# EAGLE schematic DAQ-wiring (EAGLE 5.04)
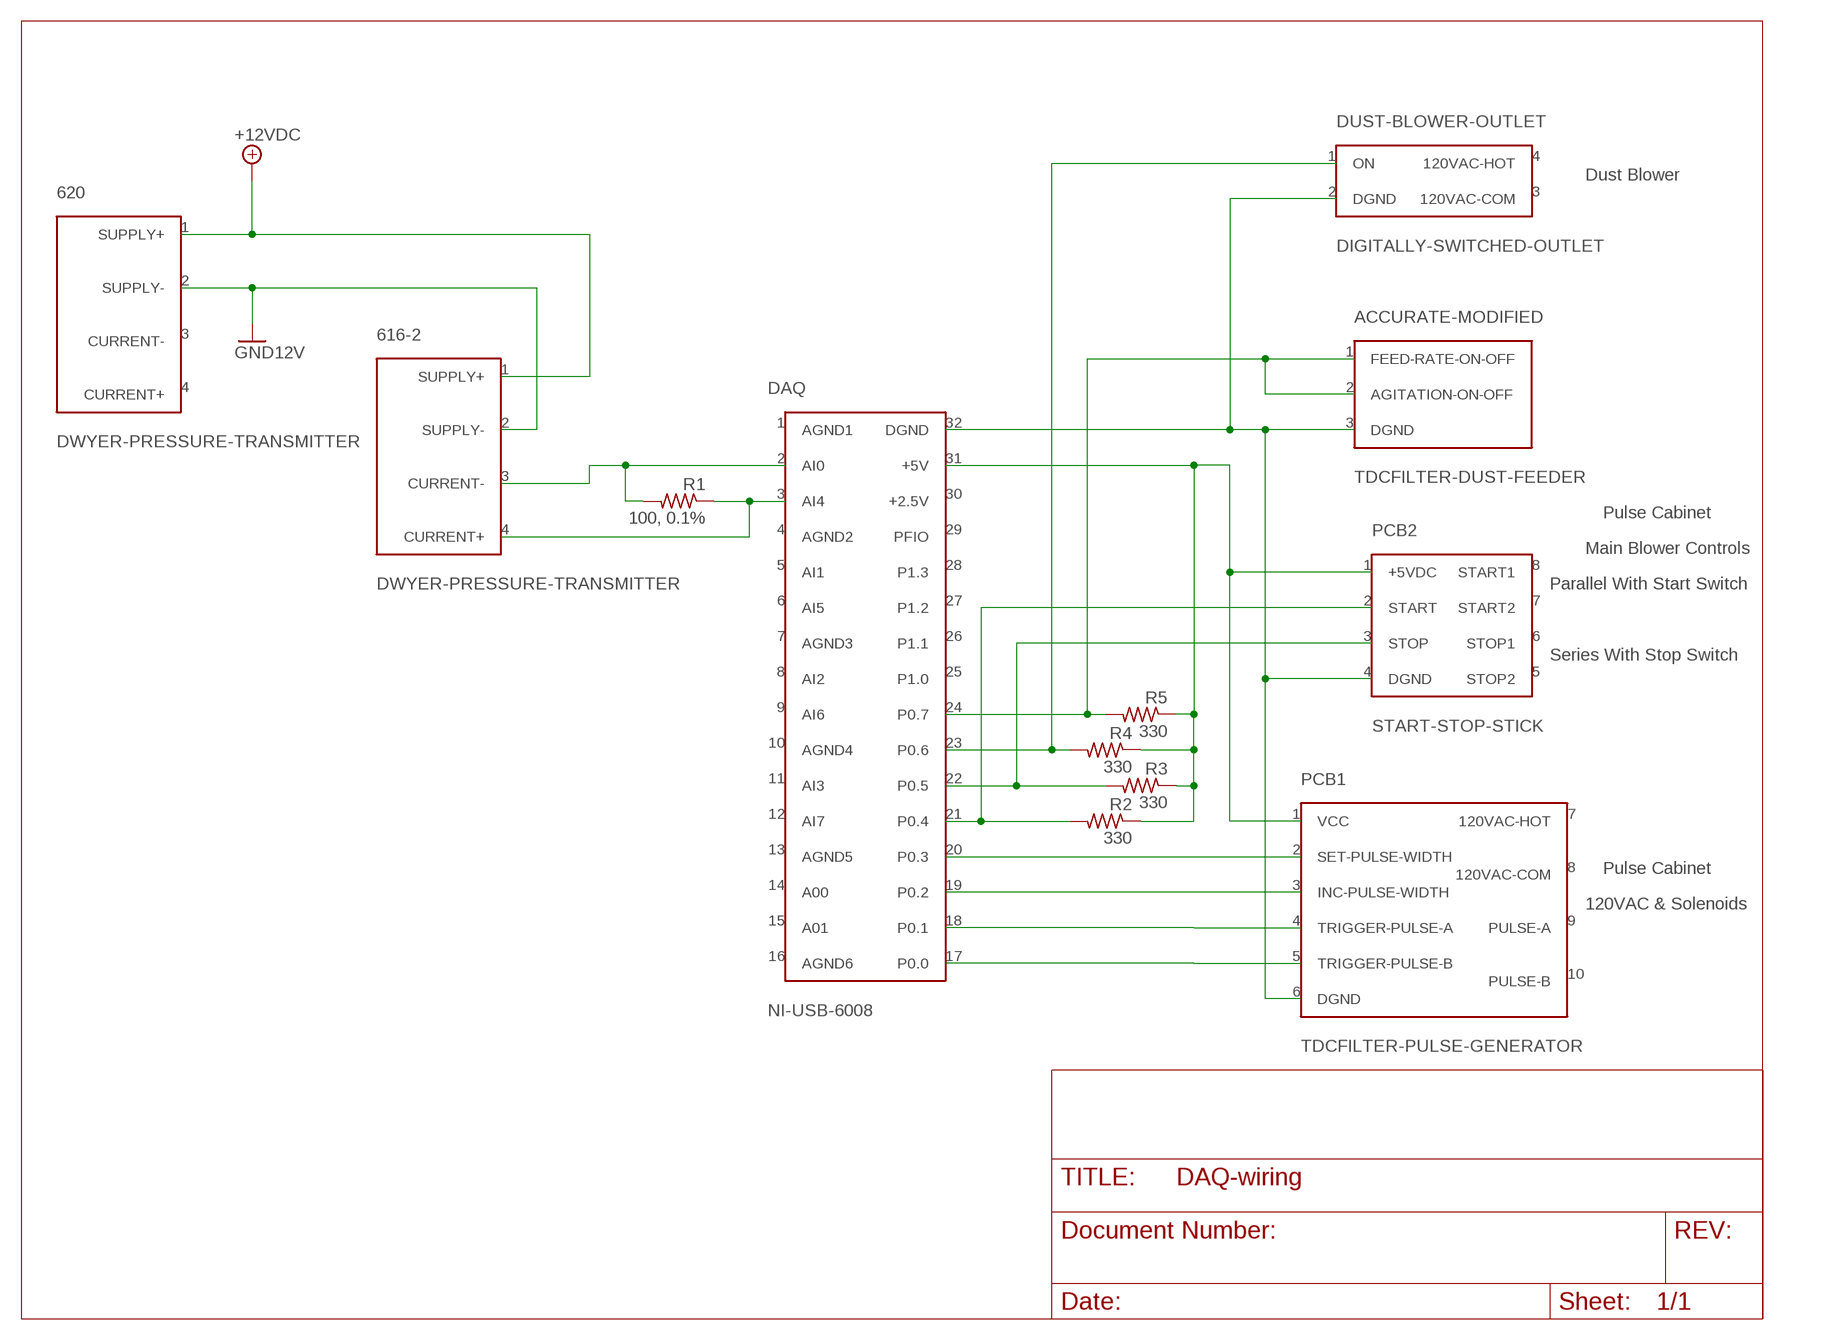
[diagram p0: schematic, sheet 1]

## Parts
616-2  DWYER-PRESSURE-TRANSMITTER  [4SIL]
620  DWYER-PRESSURE-TRANSMITTER  [4SIL]
ACCURATE-MODIFIED  TDCFILTER-DUST-FEEDER  [4SIL]
DAQ  NI-USB-6008  [32DILULTRAWIDE]
DUST-BLOWER-OUTLET  DIGITALLY-SWITCHED-OUTLET  [4DIP]
PCB1  TDCFILTER-PULSE-GENERATOR  [10SILWIDE]
PCB2  START-STOP-STICK  [8DIP]
R1  100, 0.1%  R-US_V234/12  [V234/12]
R2  330  R-US_V234/12  [V234/12]
R3  330  R-US_V234/12  [V234/12]
R4  330  R-US_V234/12  [V234/12]
R5  330  R-US_V234/12  [V234/12]

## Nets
+12V: 616-2.1(SUPPLY+) 620.1(SUPPLY+) ; supply symbol labelled +12VDC
GND: 616-2.2(SUPPLY-) 620.2(SUPPLY-) ; supply symbol labelled GND12V
N$1: 616-2.3(CURRENT-) DAQ.2(AI0) R1.2
N$2: 616-2.4(CURRENT+) DAQ.3(AI4) R1.1
N$3: DAQ.21(P0.4) PCB2.2(START) R2.2
N$4: DAQ.22(P0.5) PCB2.3(STOP) R3.2
N$5: DAQ.23(P0.6) DUST-BLOWER-OUTLET.1(ON) R4.2
N$6: ACCURATE-MODIFIED.1(FEED-RATE-ON-OFF) ACCURATE-MODIFIED.2(AGITATION-ON-OFF) DAQ.24(P0.7) R5.2
N$7: DAQ.31(+5V) PCB1.1(VCC) PCB2.1(+5VDC) R2.1 R3.1 R4.1 R5.1
N$8: ACCURATE-MODIFIED.3(DGND) DAQ.32(DGND) DUST-BLOWER-OUTLET.2(DGND) PCB1.6(DGND) PCB2.4(DGND)
N$9: DAQ.17(P0.0) PCB1.5(TRIGGER-PULSE-B)
N$10: DAQ.18(P0.1) PCB1.4(TRIGGER-PULSE-A)
N$11: DAQ.19(P0.2) PCB1.3(INC-PULSE-WIDTH)
N$12: DAQ.20(P0.3) PCB1.2(SET-PULSE-WIDTH)
Unconnected: 620.3(CURRENT-) 620.4(CURRENT+) DAQ.1(AGND1) DAQ.4(AGND2) DAQ.5(AI1) DAQ.6(AI5) DAQ.7(AGND3) DAQ.8(AI2) DAQ.9(AI6) DAQ.10(AGND4) DAQ.11(AI3) DAQ.12(AI7) DAQ.13(AGND5) DAQ.14(A00) DAQ.15(A01) DAQ.16(AGND6) DAQ.25(P1.0) DAQ.26(P1.1) DAQ.27(P1.2) DAQ.28(P1.3) DAQ.29(PFIO) DAQ.30(+2.5V) DUST-BLOWER-OUTLET.3(120VAC-COM) DUST-BLOWER-OUTLET.4(120VAC-HOT) PCB1.7(120VAC-HOT) PCB1.8(120VAC-COM) PCB1.9(PULSE-A) PCB1.10(PULSE-B) PCB2.5(STOP2) PCB2.6(STOP1) PCB2.7(START2) PCB2.8(START1)

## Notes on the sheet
- Dust Blower
- Pulse Cabinet
- Main Blower Controls
- Parallel With Start Switch
- Series With Stop Switch
- Pulse Cabinet
- 120VAC & Solenoids

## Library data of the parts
616-2 620 = trl:DWYER-PRESSURE-TRANSMITTER
ACCURATE-MODIFIED = trl:TDCFILTER-DUST-FEEDER
DAQ = trl:NI-USB-6008
DUST-BLOWER-OUTLET = trl:DIGITALLY-SWITCHED-OUTLET
PCB1 = trl:TDCFILTER-PULSE-GENERATOR
PCB2 = trl:START-STOP-STICK
R1-R5 = resistor:R-US_: RESISTOR, American symbol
